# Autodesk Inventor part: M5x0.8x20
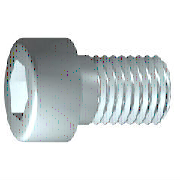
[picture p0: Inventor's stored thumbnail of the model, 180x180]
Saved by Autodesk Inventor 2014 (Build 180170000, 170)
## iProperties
IsCustomPart: 0
Created: 2009-02
Part Number: M5x0.8x20
Material: Steel, Mild
Description: 6각머리 태핑 나사
Document SubType Name: Modeling
Standard: KS B 1003
Designer: KYOUNG IL JANG
Standards Organization: KS
Language: ko-KR
Size Designation: M 5 x 20
Categories: <MemberInstance><Categories><Category DisplayName="조임쇠" InternalName="e4da775c-781d-43d5-af7c-5136215cf5a6" Mnemonic="FSTN"><Category DisplayName="볼트" InternalN
Density: 1 g/cm^3
Appearance: Metal-Steel
Author: KYOUNG IL JANG
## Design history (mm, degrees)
sketch "스케치1"
  geometry: L1 (-1.167, 0)-(20, 0); L2 (20, 0)-(20, 2.5); L3 (20, 2.5)-(2, 2.5); L4 (2, 2.5)-(1.509, 2.5); L5 (1.509, 2.5)-(0, 2.5); L6 (0, 2.5)-(0, 4.25); L7 (0, 4.25)-(-5, 4.25); L8 (-5, 4.25)-(-5, 2.309); L9 (-5, 2.309)-(-2.5, 2.309); L10 (-2.5, 2.309)-(-1.167, 0); L11 (-10, 0)-(25, 0) reference; L12 (0, -0.85)-(0, 5.1) reference; L13 (2, 2.5)-(0, 2.5)
  constraints: 22 end point, 6 parallel, 2 collinear, 2 perpendicular, 1 horizontal, 1 point on line
  dimensions: "d1" = 18 distance from line of L3.end L2 (= GEL); "d2" = 0.49086 distance of L4.end L3.end (computed from GAL); "d3" = 5 distance between parallel lines of L8 L6 (= KOH); "d4" = 2.5 distance of L8.end L9.end (= INTI); "d5" = 60 deg angle of L10 L1; "d6" = 5 diameter of L3 L1 (= GD); "d7" = 5 diameter of L5 L1 (= BDM); "d8" = 4.6188 diameter of L9 L1 (= 1.1547 x SW); "d9" = 8.5 diameter of L7 L1 (= KOD); "d26" = 20 distance between parallel lines of L12 L2 (= NLG)
revolve "본체" sketch "스케치1" stored, may be unused: angle "d10" = 90 deg
sketch "스케치2"
  geometry: L1 (0, -5.95)-(0, 5.95) reference; L2 (-5.95, 0)-(5.95, 0) reference; L3 (2.309, 0)-(1.155, -2); L4 (1.155, -2)-(-1.155, -2); L5 (-1.155, -2)-(-2.309, 0); L6 (-2.309, 0)-(-1.155, 2); L7 (-1.155, 2)-(1.155, 2); L8 (1.155, 2)-(2.309, 0); 2 further points
  constraints: 12 end point, 1 coincident, 1 horizontal alignment, 1 point on line, 12 other
extrude "슬롯" join sketch "스케치2" stored distance "d11" = 10; taper "d12" = 0 deg
workplane "Work Plane1"
fillet "Fillet2" dims "d30" = 0.1 (= R)
body "Solid1"
fillet "모깎기1" dims "d17" = 0.5 (= RR)
feature "스레드" dims "d13" = 18 (= GEL), "d14" = 0
chamfer "모따기1" distance "d15" = 0.49076 (= -0.5 x SPD + 0.5 x GD); stored, may be unused: second distance "d16" = 0.49076 (= GUL), angle "d27" = 45 deg
other parameters: "GD" = 5 (= NND) [user parameter; used in 2 equation terms], "NLG" = 20 [user parameter; used in 1 equation term], "GEL" = 18 [user parameter; used in 2 equation terms], "KOD" = 8.5 [user parameter; used in 1 equation term], "KOH" = 5 [user parameter; used in 1 equation term], "INTI" = 2.5 [user parameter; used in 1 equation term], "GAL" = 0.49076 (= 0.61345 x PTC) [user parameter; used in 1 equation term], "GUL" = 0.49076 (= 0.61345 x PTC) [user parameter; used in 1 equation term], "BDM" = 5 (= NND) [user parameter; used in 1 equation term], "SW" = 4 [user parameter; used in 2 equation terms], "RR" = 0.5 [user parameter; used in 1 equation term], "SPD" = 4.01848 (= NND - 1.2269 x PTC) [user parameter; used in 1 equation term], "d19" = 0, "d28" = 0, "d29" = 0, "R" = 0.1 [user parameter; used in 1 equation term], "PHH" = 0.2 [user parameter], "GD1" = 4.01848 (= THREADDIA - 1.2269 x PTC) [user parameter], "THREADDIA" = 5 [user parameter; used in 1 equation term], "FAWI" = 45 deg [user parameter], "TPU" = 12.5 (computed from PTC) [user parameter], "PTC" = 0.8 [user parameter; used in 5 equation terms], "NND" = 5 [user parameter; used in 3 equation terms], "TOA" = 30 deg [user parameter], "E0" = 4.62 (= 1.155 x SW) [user parameter]
